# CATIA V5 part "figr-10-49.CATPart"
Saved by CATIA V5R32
Part number: Part1
Bounding box of the stored display mesh (mm): x -75 to 75, y 0 to 282.665, z -39.154 to 114.529
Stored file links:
  D:\PROJECTS\Project 2022\CATIA V5 6R 2022\Resources\Part Files\c10_catia_v5_6r2022_prt\c10_catia_v5_6r2022_prt\figr-10-49.CATPart
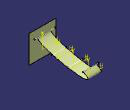
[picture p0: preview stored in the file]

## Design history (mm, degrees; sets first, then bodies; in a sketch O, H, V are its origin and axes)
Body1 (main body)
  Plane1: type Offset, RefPlane zx-plane, Offset 85
  Sketch1 on yz-plane, origin (0, 0, 0), H (0, 1, 0), V (0, 0, 1)
    line L1 (0, 114.5286) -> (0, -39.1536)
    point P1 (0, 114.5286)
    coincidence: P1 V
    vertical: L1 V
  Extrude1: Element1 Sketch1, Lim1 75, Lim2 75
  Plane2: type Offset, RefPlane Plane1, Offset 85
  Plane3: type Offset, RefPlane Plane2, Offset 85
  Sketch2 on zx-plane, origin (0, 0, 0), H (-1, 0, 0), V (0, 0, 1)
    line L1 (-43.9118, 70.4151) -> (71.5537, 70.4151)
    horizontal: L1 H
  Sketch3 on Plane1, origin (0, 85, 0), H (-1, 0, 0), V (0, 0, 1)
    line L1 (-29.1778, 30.4555) -> (46.4999, 30.4555)
    horizontal: L1 H
  Sketch4 on Plane2, origin (0, 170, 0), H (-1, 0, 0), V (0, 0, 1)
    line L1 (-27.284, 11.606) -> (54.5029, 11.606)
    horizontal: L1 H
  Sketch5 on Plane3, origin (0, 255, 0), H (-1, 0, 0), V (0, 0, 1)
    line L1 (-28.2106, 33.1442) -> (56.8447, 33.1442)
    horizontal: L1 H
  Sweep1: type Conic, Guide ({sweepconicextendedguide Guide Sketch2, Reference zx-plane, Angle 0}; Sketch3; Sketch4; Sketch5)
